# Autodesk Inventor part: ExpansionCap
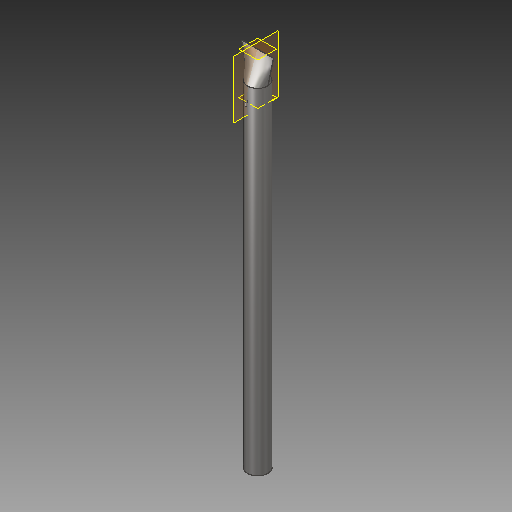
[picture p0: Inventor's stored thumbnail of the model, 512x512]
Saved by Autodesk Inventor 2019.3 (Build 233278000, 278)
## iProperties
Created: 2019-05
Part Number: ExpansionCap
Material: Steel, Galvanized
Document SubType Name: Modeling
Designer: u1426
Density: 7.85 g/cm^3
Appearance: Galvanized
ExpCapID: 1.500 in
DistLenghtStop: 24.000 in
Author: u1426
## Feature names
1. Extrusion1
2. Extrusion2
3. Hole1
4. Loft1
5. Sweep1
## Parameters: d4 = 38.89756 mm, d6 = 0, d7 = 25.4 mm, d8 = 0, d10 = 19.05 mm, d11 = 9.525 mm, d12 = 6.35 mm, d13 = 82 deg, d14 = 25.4 mm, d15 = 118 deg, d19 = 50.8 mm, d20 = 60.27161 mm, d21 = 60.27161 mm, d22 = 0, d23 = 90 deg, d24 = 0, d25 = 90 deg, d26 = -79.375 mm, d27 = 38.89756 mm, d28 = 30.1358 mm, d29 = 1.5875 mm, d30 = 22.62378 mm, d31 = 6.35 mm, d32 = 6.35 mm, d33 = 45.24756 mm, d34 = 0, d35 = 0, d36 = 25.4 mm, d37 = 3.175 mm
